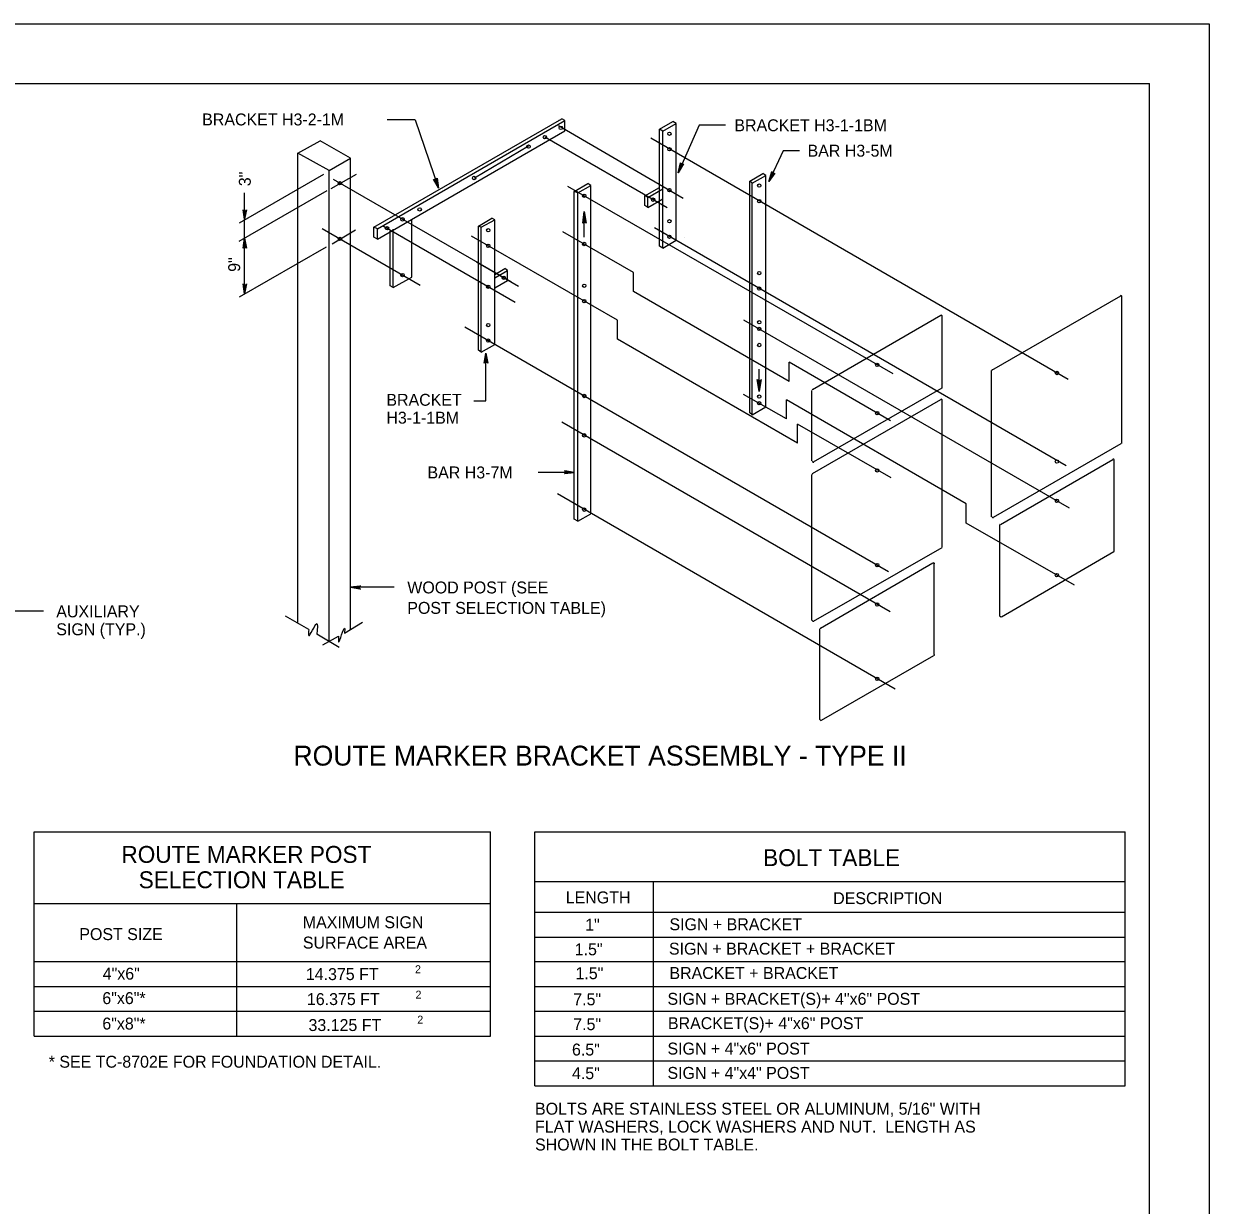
# Model space of a CAD drawing. Extents: x 648590 to 650336, y 294467 to 295061.
# Drawn here: x 649974.1 to 650272.1, y 294764.4 to 295061.4 of the extents above; entities that cross this region are included whole.
import ezdxf

# ---------------------------------------------------------------- set-up
doc = ezdxf.new("R2010")
doc.units = 0
for name, color, linetype in [('1', 7, 'Continuous'), ('2', 7, 'Continuous'), ('3', 7, 'Continuous'), ('PLT-BNDY', 7, 'Continuous')]:
    doc.layers.add(name, color=color, linetype=linetype)

msp = doc.modelspace()

# ---------------------------------------------------------------- linework, layer by layer
at = {"layer": '1'}
for p in [(649471.1, 295046.45), (650257.1, 294482.45)]:
    msp.add_line(p, (650257.1, 295046.45), dxfattribs=at)
at = {"layer": '2'}
for p, q in [((649976.66, 294858.34), (650091.4, 294858.34)), ((649976.66, 294806.97), (649976.66, 294858.34)), ((650091.4, 294806.97), (650091.4, 294858.34)), ((650102.51, 294858.34), (650250.98, 294858.34)), ((650102.51, 294794.47), (650102.51, 294858.34)), ((650250.98, 294794.47), (650250.98, 294858.34)), ((650102.51, 294845.84), (650250.98, 294845.84)), ((650132.39, 294794.47), (650132.39, 294845.72)), ((649976.66, 294840.28), (650091.4, 294840.28)), ((650027.64, 294806.84), (650027.64, 294840.16)), ((650102.51, 294838.09), (650250.98, 294838.09)), ((650102.51, 294831.84), (650250.98, 294831.84)), ((649976.66, 294825.72), (650091.4, 294825.72)), ((650102.51, 294825.72), (650250.98, 294825.72)), ((649976.66, 294819.47), (650091.4, 294819.47)), ((650102.51, 294819.47), (650250.98, 294819.47)), ((649976.66, 294813.22), (650091.4, 294813.22)), ((650102.51, 294813.22), (650250.98, 294813.22)), ((649976.66, 294806.97), (650091.4, 294806.97)), ((650102.51, 294806.97), (650250.98, 294806.97)), ((650102.51, 294800.72), (650250.98, 294800.72)), ((650102.51, 294794.47), (650250.98, 294794.47))]:
    msp.add_line(p, q, dxfattribs=at)
for points in [[(650072.48, 295037.27), (650065.41, 295037.27)], [(650072.48, 295037.27), (650078.35, 295020.15)], [(650143.89, 295035.93), (650138.57, 295023.96)], [(650150.49, 295035.93), (650143.89, 295035.93)], [(650169.1, 295029.53), (650164.97, 295029.53), (650161.35, 295021.78)], [(650139.82, 295026.09), (650139.57, 295026.09), (650138.57, 295023.96), (650139.82, 295026.09), (650139.95, 295026.21), (650138.57, 295023.96), (650139.32, 295026.21), (650139.32, 295026.34), (650138.57, 295023.96), (650139.2, 295026.46), (650139.32, 295026.34)], [(650077.85, 295022.4), (650077.72, 295022.28), (650078.35, 295020.15), (650077.85, 295022.4), (650077.97, 295022.65), (650078.35, 295020.15), (650077.47, 295022.28), (650077.35, 295022.28), (650078.35, 295020.15), (650077.1, 295022.28), (650077.35, 295022.28)], [(650162.72, 295023.78), (650162.47, 295023.78), (650161.35, 295021.78), (650162.72, 295023.78), (650162.85, 295023.9), (650161.35, 295021.78), (650162.22, 295023.9), (650162.1, 295024.03), (650161.35, 295021.78), (650162.1, 295024.28), (650162.1, 295024.03)], [(650087.22, 294966.65), (650090.22, 294966.65), (650090.22, 294978.65)], [(650089.97, 294976.28), (650090.1, 294976.4), (650090.22, 294978.65), (650089.97, 294976.28), (650089.85, 294976.15), (650090.22, 294978.65), (650090.35, 294976.4), (650090.6, 294976.28), (650090.22, 294978.65), (650090.72, 294976.15), (650090.6, 294976.28)], [(650112.47, 294948.65), (650103.35, 294948.65)], [(650110.1, 294949.03), (650110.22, 294948.78), (650112.47, 294948.65), (650110.1, 294949.03), (650109.97, 294949.03), (650112.47, 294948.65), (650110.22, 294948.53), (650110.1, 294948.4), (650112.47, 294948.65), (650109.97, 294948.28), (650110.1, 294948.4)], [(650058.6, 294919.4), (650058.47, 294919.65), (650056.22, 294919.78), (650058.6, 294919.4), (650058.72, 294919.28), (650056.22, 294919.78), (650058.47, 294919.9), (650058.6, 294920.03), (650056.22, 294919.78), (650058.72, 294920.15), (650058.6, 294920.03)], [(650067.16, 294919.78), (650056.22, 294919.78)], [(649979.04, 294913.79), (649968.97, 294913.79)]]:
    msp.add_lwpolyline(points, dxfattribs=at)
at = {"layer": '3'}
for p, q in [((650062.1, 295010.28), (650109.35, 295037.53)), ((650062.97, 295009.9), (650110.1, 295037.15)), ((650108.6, 295037.28), (650108.6, 295037.28)), ((650110.1, 295037.15), (650109.35, 295037.53)), ((650110.1, 295034.53), (650110.1, 295037.15)), ((650133.85, 295034.9), (650137.22, 295036.9)), ((650138.1, 295036.4), (650137.22, 295036.9)), ((650062.97, 295007.28), (650110.1, 295034.53)), ((650139.85, 295017.53), (650108.47, 295035.78)), ((650109.47, 295034.28), (650109.47, 295034.28)), ((650133.85, 295005.53), (650133.85, 295034.9)), ((650134.72, 295034.4), (650133.85, 295034.9)), ((650134.72, 295034.4), (650138.1, 295036.4)), ((650134.72, 295005.03), (650134.72, 295034.4)), ((650138.1, 295007.03), (650138.1, 295036.4)), ((650042.97, 295028.9), (650048.6, 295032.03)), ((650056.22, 295027.65), (650048.6, 295032.03)), ((650135.85, 295015.15), (650105.1, 295032.9)), ((650236.6, 294972.03), (650131.72, 295032.65)), ((650042.97, 294910.65), (650042.97, 295028.9)), ((650050.85, 295024.53), (650042.97, 295028.9)), ((650100.97, 295030.65), (650087.35, 295022.65)), ((650050.85, 295024.53), (650056.22, 295027.65)), ((650056.22, 294909.28), (650056.22, 295027.65)), ((650028.35, 295011.4), (650049.47, 295023.65)), ((650050.85, 294906.03), (650050.85, 295024.53)), ((650051.35, 295020.03), (650057.72, 295023.65)), ((650096.6, 294996.53), (650051.97, 295022.28)), ((650156.6, 295021.9), (650159.85, 295023.78)), ((650157.22, 295021.4), (650160.6, 295023.28)), ((650160.6, 295023.28), (650159.85, 295023.78)), ((650160.6, 294965.15), (650160.6, 295023.28)), ((650028.22, 295006.78), (650050.35, 295019.53)), ((650053.6, 295021.4), (650053.6, 295021.4)), ((650192.6, 294973.4), (650110.85, 295020.53)), ((650112.47, 295019.28), (650115.85, 295021.28)), ((650112.47, 294936.9), (650112.47, 295019.28)), ((650113.35, 295018.9), (650112.47, 295019.28)), ((650113.35, 295018.9), (650116.6, 295020.78)), ((650116.6, 295020.78), (650115.85, 295021.28)), ((650116.6, 294938.28), (650116.6, 295020.78)), ((650130.22, 295018.15), (650133.85, 295020.28)), ((650130.97, 295017.78), (650134.72, 295019.9)), ((650156.6, 294963.65), (650156.6, 295021.9)), ((650157.22, 295021.4), (650156.6, 295021.9)), ((650157.22, 294963.15), (650157.22, 295021.4)), ((650029.6, 295007.57), (650029.6, 295018.9)), ((650113.35, 294936.4), (650113.35, 295018.9)), ((650130.97, 295017.78), (650130.22, 295018.28)), ((650130.22, 295015.78), (650130.22, 295018.15)), ((650130.97, 295015.28), (650130.97, 295017.78)), ((650130.97, 295015.28), (650134.72, 295017.4)), ((650114.97, 295007.78), (650114.97, 295014.28)), ((650130.97, 295015.28), (650130.22, 295015.78)), ((650062.97, 295009.9), (650062.1, 295010.28)), ((650062.1, 295007.78), (650062.1, 295010.28)), ((650097.6, 294991.4), (650064.22, 295010.65)), ((650069.35, 295012.28), (650069.35, 295012.28)), ((650071.6, 294997.78), (650071.6, 295012.28)), ((650088.35, 295010.53), (650091.72, 295012.53)), ((650088.35, 294979.4), (650088.35, 295010.53)), ((650089.1, 295010.28), (650088.35, 295010.53)), ((650089.1, 295010.28), (650092.47, 295012.15)), ((650089.1, 294978.9), (650089.1, 295010.28)), ((650092.47, 295012.15), (650091.72, 295012.53)), ((650092.47, 294980.78), (650092.47, 295012.15)), ((650236.1, 294950.28), (650132.6, 295010.15)), ((650029.6, 294993.53), (650029.6, 295007.53)), ((650073.72, 294995.65), (650049.1, 295009.9)), ((650051.6, 295006.15), (650057.47, 295009.65)), ((650053.6, 295007.28), (650053.6, 295007.28)), ((650062.97, 295007.28), (650062.1, 295007.78)), ((650062.97, 295007.28), (650062.97, 295009.9)), ((650062.97, 295009.9), (650062.97, 295009.9)), ((650066.22, 294995.53), (650066.22, 295009.28)), ((650066.97, 294995.15), (650066.97, 295009.78)), ((650069.35, 295008.03), (650069.35, 295008.03)), ((650123.35, 294986.9), (650086.6, 295008.03)), ((650127.35, 294998.9), (650109.6, 295009.15)), ((650140.22, 295007.78), (650140.22, 295007.78)), ((650028.35, 294992.78), (650050.22, 295005.4)), ((650134.72, 295005.03), (650133.85, 295005.53)), ((650134.72, 295005.03), (650138.1, 295007.03)), ((650098.47, 294995.4), (650087.85, 295001.53)), ((650069.35, 294998.28), (650069.35, 294998.28)), ((650092.47, 294998.4), (650094.97, 294999.9)), ((650092.47, 294997.53), (650095.72, 294999.4)), ((650095.72, 294999.4), (650094.97, 294999.9)), ((650095.72, 294996.9), (650095.72, 294999.4)), ((650127.35, 294994.15), (650127.35, 294998.9)), ((650066.97, 294995.15), (650066.22, 294995.53)), ((650066.97, 294995.15), (650071.6, 294997.78)), ((650092.47, 294995.03), (650095.72, 294996.9)), ((650094.72, 294997.65), (650094.72, 294997.65)), ((650094.72, 294993.28), (650094.72, 294993.28)), ((650166.47, 294971.53), (650127.35, 294994.15)), ((650217.47, 294974.4), (650249.85, 294993.03)), ((650250.1, 294956.15), (650250.1, 294992.78)), ((650123.35, 294982.15), (650123.35, 294986.9)), ((650236.97, 294939.65), (650155.1, 294986.9)), ((650172.35, 294969.53), (650204.6, 294988.15)), ((650204.97, 294970.03), (650204.97, 294987.9)), ((650191.47, 294923.65), (650084.97, 294985.15)), ((650089.1, 294978.9), (650092.47, 294980.78)), ((650168.6, 294956.03), (650123.35, 294982.15)), ((650089.1, 294978.9), (650088.35, 294979.4)), ((650158.97, 294969.03), (650158.97, 294974.65)), ((650191.97, 294961.65), (650166.47, 294976.4)), ((650166.47, 294971.53), (650166.47, 294976.4)), ((650217.35, 294937.53), (650217.35, 294974.28)), ((650172.22, 294951.53), (650172.22, 294969.28)), ((650172.6, 294951.28), (650204.97, 294969.9)), ((650165.85, 294962.15), (650154.97, 294968.28)), ((650165.85, 294962.15), (650165.85, 294966.9)), ((650210.97, 294940.78), (650165.85, 294966.9)), ((650172.35, 294948.4), (650204.6, 294967.03)), ((650204.97, 294930.03), (650204.97, 294966.78)), ((650157.22, 294963.15), (650156.6, 294963.65)), ((650157.22, 294963.15), (650160.6, 294965.15)), ((650191.85, 294913.65), (650109.35, 294961.28)), ((650192.1, 294947.28), (650168.6, 294960.78)), ((650168.6, 294956.03), (650168.6, 294960.78)), ((650217.85, 294937.4), (650249.97, 294955.9)), ((650219.6, 294935.53), (650247.85, 294951.9)), ((650248.22, 294929.03), (650248.22, 294951.78)), ((650172.22, 294911.4), (650172.22, 294948.15)), ((650193.1, 294894.15), (650108.22, 294943.28)), ((650210.97, 294935.9), (650210.97, 294940.78)), ((650113.35, 294936.4), (650112.47, 294936.9)), ((650113.35, 294936.4), (650116.6, 294938.28)), ((650238.22, 294920.28), (650210.97, 294935.9)), ((650219.47, 294912.65), (650219.47, 294935.4)), ((650172.6, 294911.28), (650204.97, 294929.78)), ((650219.85, 294912.4), (650248.1, 294928.78)), ((650174.35, 294909.53), (650202.6, 294925.9)), ((650202.97, 294902.9), (650202.97, 294925.65)), ((650045.72, 294909.15), (650039.85, 294912.53)), ((650054.72, 294908.28), (650059.22, 294911.03)), ((650174.22, 294886.53), (650174.22, 294909.28)), ((650053.35, 294904.65), (650047.72, 294908.03)), ((650049.22, 294905.28), (650053.22, 294907.53)), ((650174.6, 294886.4), (650202.85, 294902.65))]:
    msp.add_line(p, q, dxfattribs=at)
for points in [[(650029.97, 295014.53), (650029.85, 295014.53), (650029.6, 295012.28), (650029.97, 295014.53), (650030.1, 295014.65), (650029.6, 295012.28), (650029.6, 295014.53), (650029.35, 295014.53), (650029.6, 295012.28), (650029.22, 295014.65), (650029.35, 295014.53)], [(650114.72, 295011.4), (650114.85, 295011.53), (650114.97, 295014.28), (650114.72, 295011.4), (650114.6, 295011.28), (650114.97, 295014.28), (650115.1, 295011.53), (650115.22, 295011.53), (650114.97, 295014.28), (650115.47, 295011.28), (650115.22, 295011.53)], [(650029.35, 295005.15), (650029.47, 295005.28), (650029.6, 295007.53), (650029.35, 295005.15), (650029.22, 295005.03), (650029.6, 295007.53), (650029.72, 295005.28), (650029.97, 295005.15), (650029.6, 295007.53), (650030.1, 295005.03), (650029.97, 295005.15)], [(650029.97, 294995.9), (650029.85, 294995.78), (650029.6, 294993.53), (650029.97, 294995.9), (650030.1, 294996.03), (650029.6, 294993.53), (650029.6, 294995.78), (650029.35, 294995.9), (650029.6, 294993.53), (650029.22, 294996.03), (650029.35, 294995.9)], [(650159.35, 294971.78), (650159.1, 294971.65), (650158.97, 294969.03), (650159.35, 294971.78), (650159.47, 294972.03), (650158.97, 294969.03), (650158.85, 294971.65), (650158.6, 294971.78), (650158.97, 294969.03), (650158.47, 294972.03), (650158.6, 294971.78)]]:
    msp.add_lwpolyline(points, dxfattribs=at)
for centre in [(650109.09, 295035.28), (650136.39, 295033.79), (650100.98, 295030.56), (650105.08, 295032.93), (650136.38, 295029.89), (650087.29, 295022.66), (650053.56, 295021.35), (650136.38, 295019.6), (650158.97, 295020.75), (650114.98, 295018.21), (650132.28, 295017.22), (650158.96, 295016.85), (650073.6, 295014.77), (650065.39, 295010.03), (650069.29, 295012.28), (650136.39, 295011.79), (650053.56, 295007.35), (650090.84, 295009.52), (650136.38, 295007.9), (650090.84, 295005.62), (650114.98, 295006.07), (650069.29, 294998.27), (650158.97, 294998.76), (650090.84, 294995.33), (650094.74, 294997.58), (650114.98, 294995.59), (650158.96, 294994.86), (650114.98, 294991.7), (650158.96, 294986.41), (650090.84, 294985.7), (650158.96, 294984.73), (650090.84, 294981.8), (650158.96, 294980.68), (650188.63, 294975.68), (650233.79, 294973.65), (650114.98, 294967.87), (650158.97, 294967.73), (650158.97, 294966.05), (650188.63, 294963.55), (650114.98, 294957.98), (650233.79, 294951.41), (650188.63, 294949.16), (650233.79, 294941.52), (650114.98, 294939.3), (650188.63, 294925.35), (650233.79, 294922.84), (650188.63, 294915.46), (650188.63, 294896.77)]:
    msp.add_circle(centre, 0.428, dxfattribs=at)
for centre, start, end in [((650249.89, 294992.86), 0, 119.9855), ((650204.73, 294987.92), 0, 119.9917), ((650217.69, 294974.28), 120.0061, 180), ((650172.53, 294969.34), 119.9995, 180), ((650204.73, 294970.07), 299.9933, 0), ((650204.73, 294966.8), 0, 119.999), ((650249.89, 294956.13), 299.9962, 0), ((650172.53, 294951.49), 180, 299.9946), ((650247.94, 294951.74), 0, 119.9857), ((650172.53, 294948.21), 120.001, 180), ((650217.69, 294937.55), 180, 299.9902), ((650219.63, 294935.4), 119.9982, 180), ((650204.73, 294930.07), 299.9789, 0), ((650247.94, 294928.96), 299.9948, 0), ((650202.79, 294925.67), 0, 119.9851), ((650219.63, 294912.62), 180, 299.9954), ((650172.53, 294911.48), 180, 299.9917), ((650174.48, 294909.34), 119.9949, 180), ((650202.79, 294902.89), 299.9719, 0), ((650174.48, 294886.56), 180, 299.9955)]:
    msp.add_arc(centre, 0.249, start, end, dxfattribs=at)
for points in [[(650045.72, 294909.15), (650045.72, 294907.65), (650047.72, 294910.65), (650047.72, 294908.03)], [(650053.22, 294907.53), (650053.22, 294906.03), (650054.72, 294909.53), (650054.72, 294908.28)]]:
    msp.add_spline(points, degree=3, dxfattribs=at)
at = {"layer": 'PLT-BNDY'}
msp.add_lwpolyline([(649431.1, 295061.45), (650272.1, 295061.45), (650272.1, 294467.45), (649431.1, 294467.45)], close=True, dxfattribs=at)

# ---------------------------------------------------------------- texts
at = {"layer": '2'}
for s, height, p in [('ROUTE MARKER BRACKET ASSEMBLY - TYPE II', 5, (650041.86, 294874.97)), ('LENGTH', 3, (650110.32, 294840.33)), ('DESCRIPTION', 3, (650177.55, 294840.14)), ('MAXIMUM SIGN', 3, (650044.23, 294834.1)), ('1"', 3, (650115.21, 294833.47)), ('SIGN + BRACKET', 3, (650136.39, 294833.58)), ('POST SIZE', 3, (649988.05, 294831.11)), ('SURFACE AREA', 3, (650044.23, 294828.98)), ('1.5"', 3, (650112.58, 294827.28)), ('SIGN + BRACKET + BRACKET', 3, (650136.26, 294827.45)), ('4"x6"', 3, (649993.93, 294821.17)), ('14.375 FT ', 3, (650044.99, 294821.05)), ('2', 2, (650072.43, 294822.79)), ('1.5"', 3, (650112.77, 294821.28)), ('BRACKET + BRACKET', 3, (650136.39, 294821.33)), ('6"x6"*', 3, (649993.83, 294815.02)), ('16.375 FT ', 3, (650045.26, 294814.77)), ('2', 2, (650072.56, 294816.39)), ('7.5"', 3, (650112.21, 294814.72)), ('SIGN + BRACKET(S)+ 4"x6" POST', 3, (650135.89, 294814.84)), ('6"x8"*', 3, (649993.83, 294808.62)), ('33.125 FT ', 3, (650045.65, 294808.25)), ('2', 2, (650073, 294810.11)), ('7.5"', 3, (650112.21, 294808.47)), ('BRACKET(S)+ 4"x6" POST', 3, (650136.01, 294808.72)), ('6.5"', 3, (650111.89, 294802.09)), ('SIGN + 4"x6" POST', 3, (650135.89, 294802.34)), ('4.5"', 3, (650111.89, 294796.15)), ('SIGN + 4"x4" POST', 3, (650135.89, 294796.22)), ('BOLTS ARE STAINLESS STEEL OR ALUMINUM, 5/16" WITH', 3, (650102.6, 294787.22)), ('FLAT WASHERS, LOCK WASHERS AND NUT.  LENGTH AS', 3, (650102.6, 294782.72)), ('SHOWN IN THE BOLT TABLE.', 3, (650102.6, 294778.22))]:
    msp.add_text(s, height=height, dxfattribs=at).set_placement(p)
at = {"layer": '3'}
for s, height, p in [('BRACKET H3-2-1M', 3, (650018.93, 295035.88)), ('BRACKET H3-1-1BM', 3, (650152.71, 295034.42)), ('BAR H3-5M', 3, (650171.11, 295028.03)), ('BRACKET', 3, (650065.23, 294965.41)), ('H3-1-1BM', 3, (650065.23, 294960.91)), ('BAR H3-7M', 3, (650075.57, 294947.15)), ('WOOD POST (SEE', 3, (650070.49, 294918.24)), ('AUXILIARY', 3, (649982.25, 294912.23)), ('POST SELECTION TABLE)', 3, (650070.49, 294913.11)), ('SIGN (TYP.)', 3, (649982.25, 294907.73)), ('ROUTE MARKER POST', 4.25, (649998.62, 294850.52)), ('BOLT TABLE', 4.25, (650159.94, 294849.7)), ('SELECTION TABLE', 4.25, (650002.97, 294844.15)), ('* SEE TC-8702E FOR FOUNDATION DETAIL.', 3, (649980.35, 294799.03))]:
    msp.add_text(s, height=height, dxfattribs=at).set_placement(p)
for s, p in [('3"', (650031.15, 295020.6)), ('9"', (650028.47, 294999.08))]:
    msp.add_text(s, height=3, rotation=90, dxfattribs=at).set_placement(p)

doc.saveas('drawing.dxf')
